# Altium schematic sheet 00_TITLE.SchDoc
size 420 x 297 mm
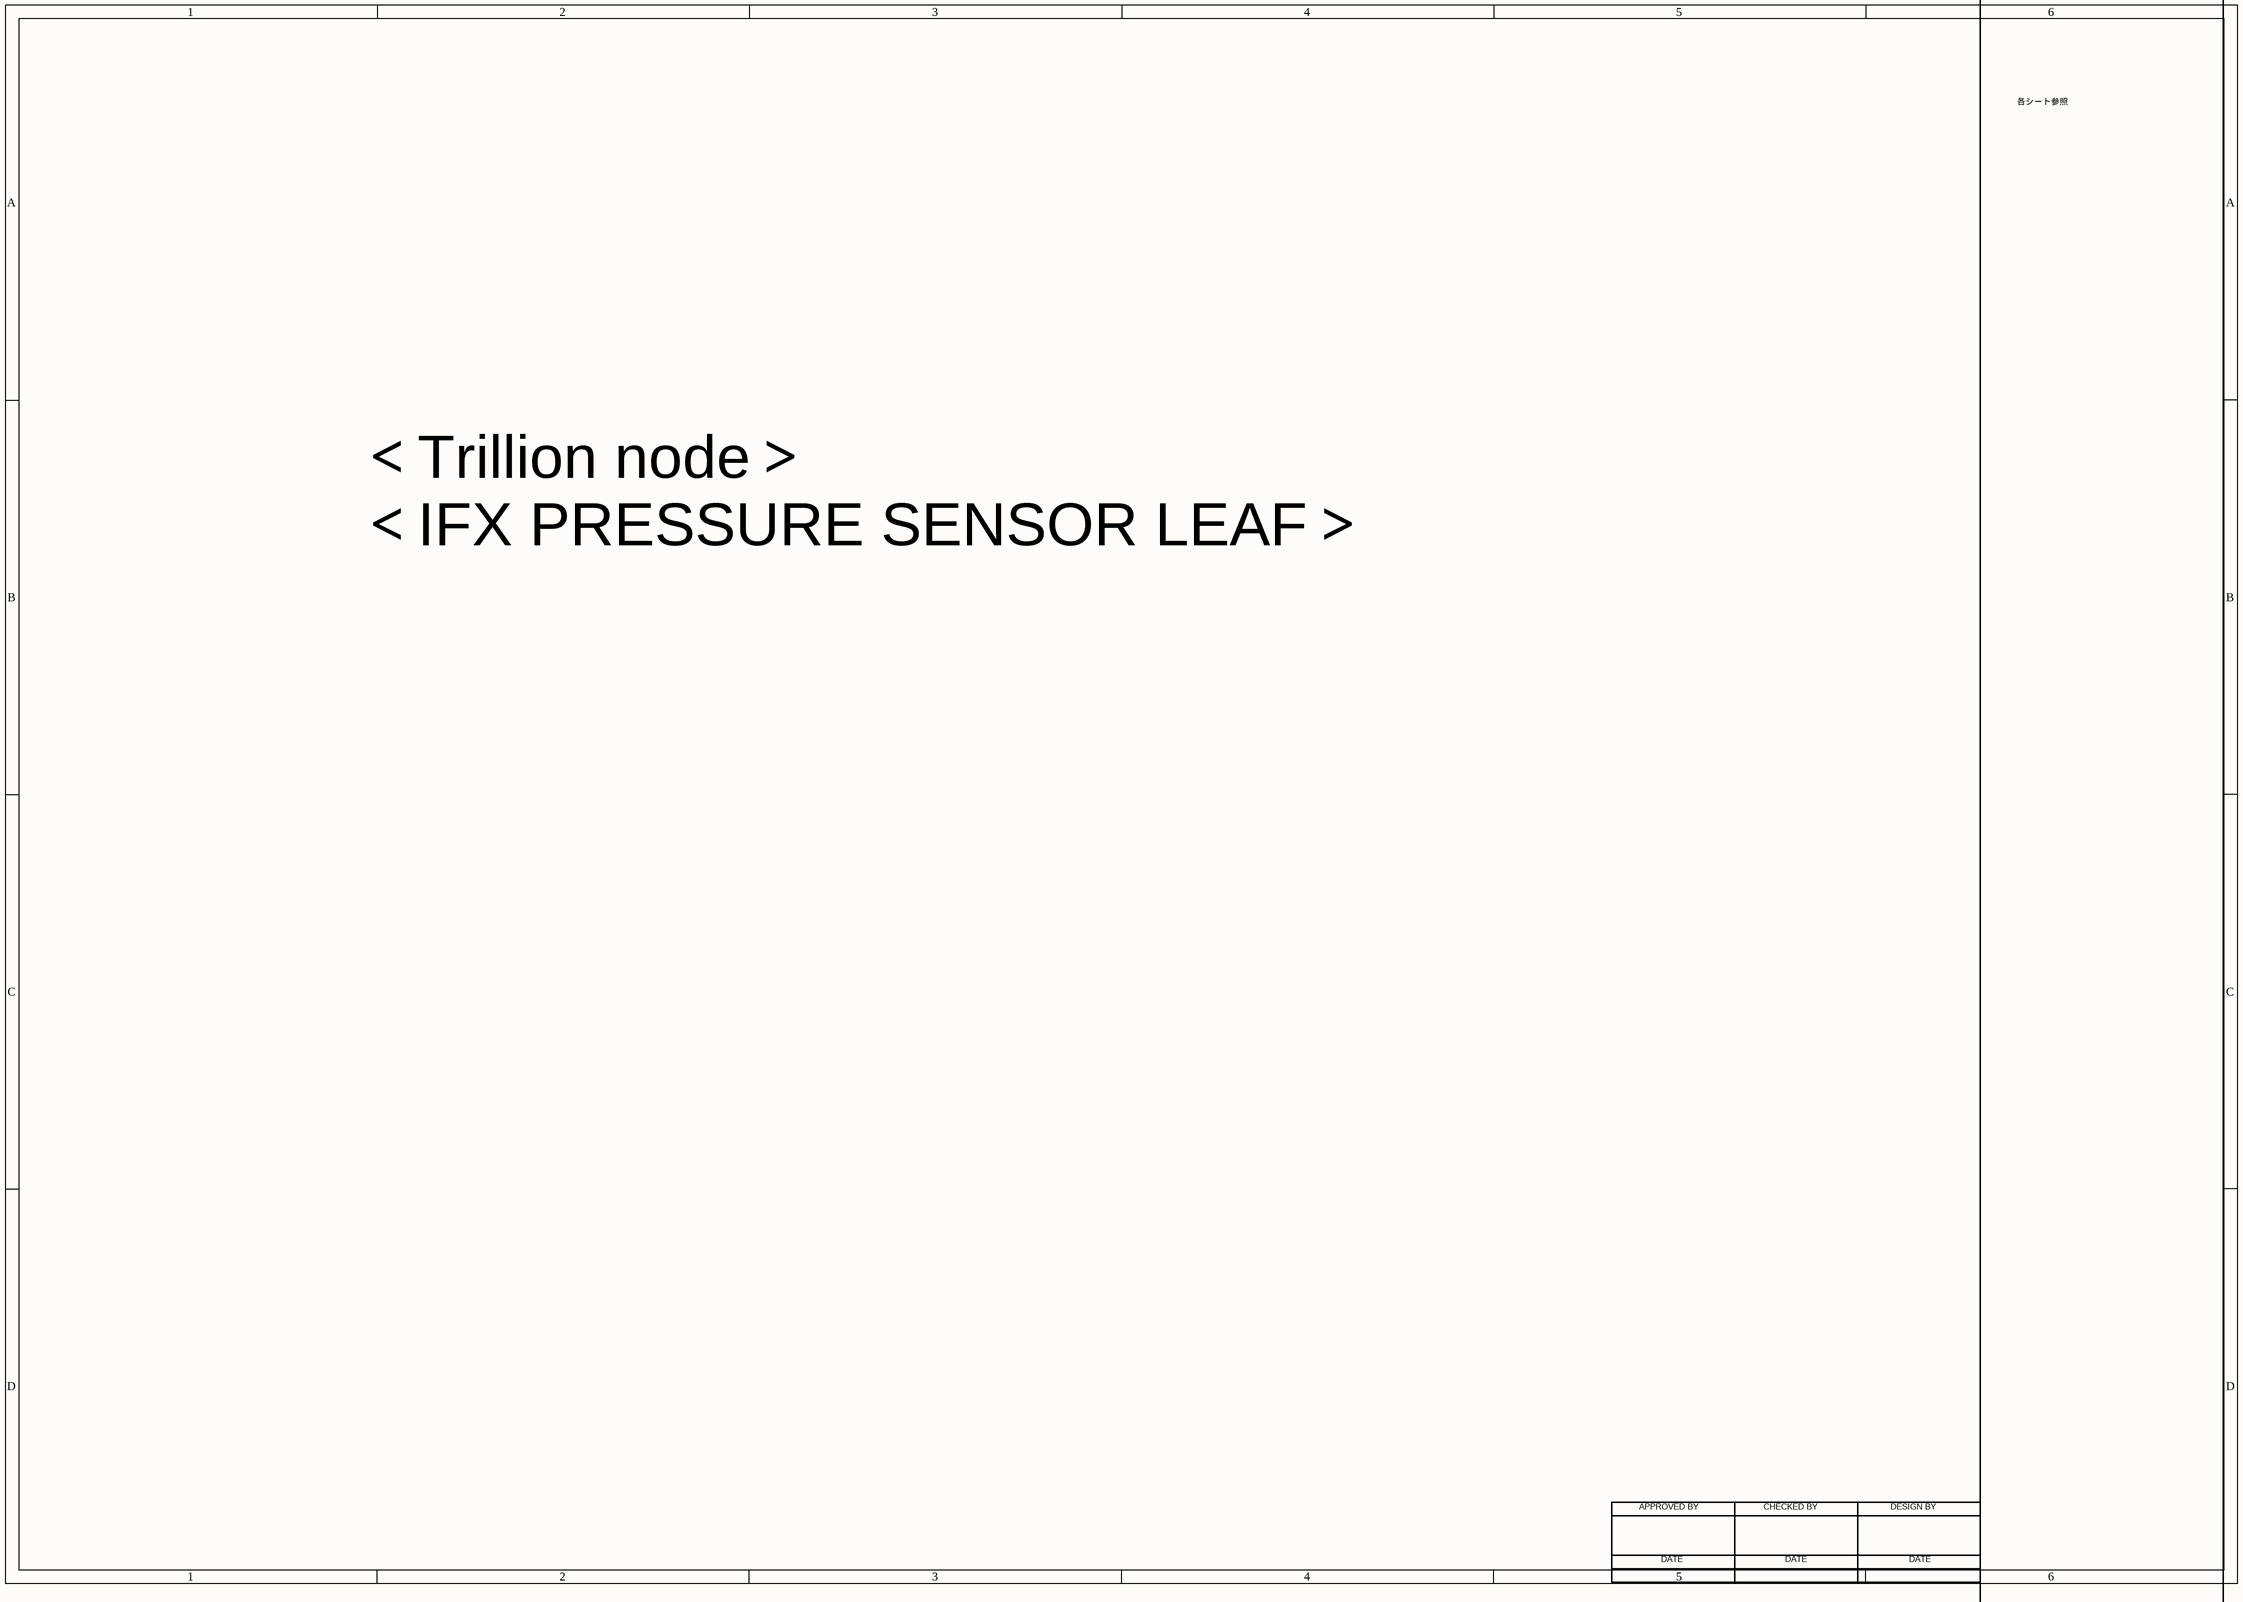
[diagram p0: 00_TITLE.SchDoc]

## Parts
(Parts that share a designator on the sheet are numbered #1, #2 ... from top to bottom, then left to right.)
*#1  TitleBlock_NEXTY-Ele_APPLOBED  (value not drawn)  (graphical)
*#2  Confidential: NEXTY Electronics Corporation Confidential  RevCode: 01  Page Size: A3  Page Number: 1  Page Count: 3  Project Name: Trillion Node  Project ID: REF051  Sheet Name: TITLE  Schematic No.: REF051-SCH013  (hidden comment: TitleBlock_NEXTY-Ele)  (graphical)

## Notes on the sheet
- 各シート参照
- ＜Trillion node＞
  ＜IFX PRESSURE SENSOR LEAF＞

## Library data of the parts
*#1 = TitleBlock_NEXTY-Ele_APPLOBED: Sample: 例; Histry_First: 完成___Rev1.0; Date2: △△△△年△△月△△日; RevChange: Rev1.0 → 1.1; Histry: B-3_Net___PG0 → PG1; Page Size: A; Page Number: N; Page Count: C; date_drawn: (     /    /   )
*#2 = TitleBlock_NEXTY-Ele: Sample: 例; Histry_First: 完成___Rev1.0; Date2: △△△△年△△月△△日; RevChange: Rev1.0 → 1.1; Histry: B-3_Net___PG0 → PG1; date_drawn: (     /    /   )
